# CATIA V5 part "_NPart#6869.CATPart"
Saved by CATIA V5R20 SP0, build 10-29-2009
Part number: 1bolaØ2,3
Revision: ANY
Definition: UNKNOWN
Nomenclature: 1bolaØ2,3
Source: Unknown
Bounding box of the stored display mesh (mm): x -1.19 to 1.19, y -1.19 to 1.19, z -1.19 to 1.19
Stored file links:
  C:\Users\Utente\Desktop\IO LAVORO\3D X SITO CF\CUMSA\3D files AE\AE 031620\_NPart#6869.CATPart
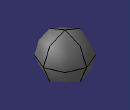
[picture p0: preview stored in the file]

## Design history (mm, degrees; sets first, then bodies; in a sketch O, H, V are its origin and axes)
Body1 "Revolución1" (main body)
  Solid1: solid without history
